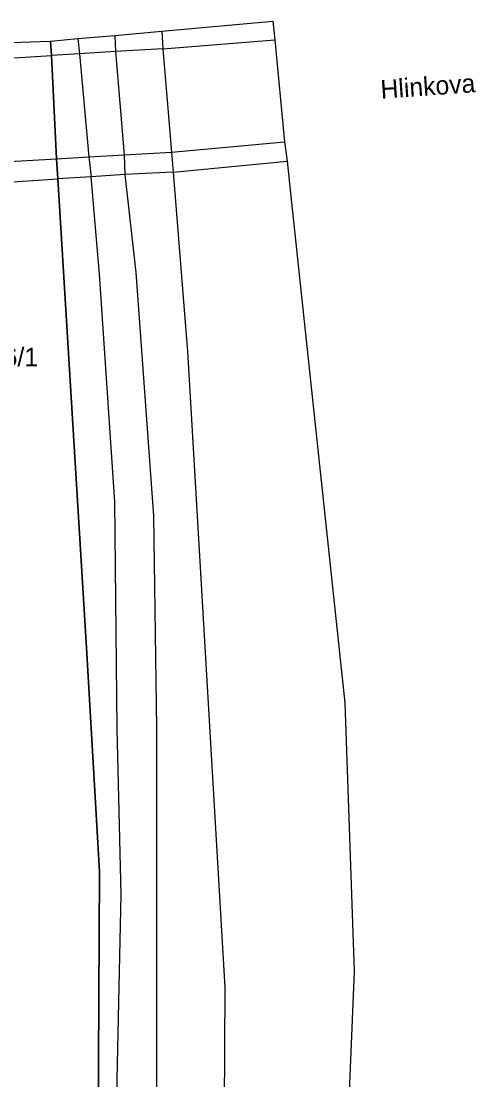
# Model space of a CAD drawing. Extents: x -262657 to -261595, y -1238015 to -1237156.
# Drawn here: x -262379.8 to -262330.6, y -1237270.1 to -1237155.7 of the extents above; entities that cross this region are included whole.
import ezdxf

# ---------------------------------------------------------------- set-up
doc = ezdxf.new("R2010")
doc.units = 0
for name, color, linetype in [('body_kn', 7, 'Continuous'), ('kladpar_hranice', 7, 'Continuous'), ('kladpar_parcelnecisla', 7, 'Continuous'), ('kladpar_plochy', 7, 'Continuous'), ('popisy', 7, 'Continuous'), ('zappar_hrandruhpozemk', 7, 'Continuous')]:
    doc.layers.add(name, color=color, linetype=linetype)

msp = doc.modelspace()

# ---------------------------------------------------------------- linework, layer by layer
at = {"layer": 'body_kn'}
for p, q in [((-262352.58, -1237155.66), (-262352.58, -1237155.66)), ((-262364.61, -1237156.73), (-262364.61, -1237156.73)), ((-262364.61, -1237156.73), (-262364.61, -1237156.73)), ((-262376.63, -1237157.82), (-262376.63, -1237157.82)), ((-262373.68, -1237157.55), (-262373.68, -1237157.55)), ((-262373.68, -1237157.55), (-262373.68, -1237157.55)), ((-262369.69, -1237157.2), (-262369.69, -1237157.2)), ((-262369.69, -1237157.2), (-262369.69, -1237157.2)), ((-262352.38, -1237157.68), (-262352.38, -1237157.68)), ((-262376.54, -1237159.38), (-262376.54, -1237159.38)), ((-262373.49, -1237159.2), (-262373.49, -1237159.2)), ((-262369.59, -1237158.94), (-262369.59, -1237158.94)), ((-262364.49, -1237158.66), (-262364.49, -1237158.66)), ((-262364.49, -1237158.66), (-262364.49, -1237158.66)), ((-262351.33, -1237168.7), (-262351.33, -1237168.7)), ((-262375.97, -1237170.53), (-262375.97, -1237170.53)), ((-262375.97, -1237170.53), (-262375.97, -1237170.53)), ((-262372.49, -1237170.32), (-262372.49, -1237170.32)), ((-262372.49, -1237170.32), (-262372.49, -1237170.32)), ((-262368.66, -1237170.11), (-262368.66, -1237170.11)), ((-262368.66, -1237170.11), (-262368.66, -1237170.11)), ((-262363.53, -1237169.82), (-262363.53, -1237169.82)), ((-262363.53, -1237169.82), (-262363.53, -1237169.82)), ((-262351.05, -1237170.78), (-262351.05, -1237170.78)), ((-262363.37, -1237171.97), (-262363.37, -1237171.97)), ((-262363.37, -1237171.97), (-262363.37, -1237171.97)), ((-262375.83, -1237172.72), (-262375.83, -1237172.72)), ((-262372.23, -1237172.48), (-262372.23, -1237172.48)), ((-262368.59, -1237172.23), (-262368.59, -1237172.23)), ((-262368.59, -1237172.23), (-262368.59, -1237172.23)), ((-262350.64, -1237174.58), (-262350.64, -1237174.58)), ((-262350.32, -1237177.64), (-262350.32, -1237177.64)), ((-262371.34, -1237183.02), (-262371.34, -1237183.02)), ((-262367.41, -1237182.84), (-262367.41, -1237182.84)), ((-262361.8, -1237191.39), (-262361.8, -1237191.39)), ((-262369.67, -1237207.63), (-262369.67, -1237207.63)), ((-262365.48, -1237209.15), (-262365.48, -1237209.15)), ((-262372.75, -1237223.4), (-262372.75, -1237223.4)), ((-262344.8, -1237229.34), (-262344.8, -1237229.34)), ((-262369.44, -1237232.16), (-262369.44, -1237232.16)), ((-262365.18, -1237232.08), (-262365.18, -1237232.08)), ((-262371.35, -1237247.59), (-262371.35, -1237247.59)), ((-262368.99, -1237250.08), (-262368.99, -1237250.08)), ((-262343.78, -1237258.35), (-262343.78, -1237258.35)), ((-262343.78, -1237258.35), (-262343.78, -1237258.35)), ((-262357.78, -1237260.12), (-262357.78, -1237260.12))]:
    msp.add_line(p, q, dxfattribs=at)
at = {"layer": 'kladpar_hranice'}
for points in [[(-262372.75, -1237403.11), (-262372.62, -1237392.55), (-262371.68, -1237316.24), (-262371.35, -1237247.59), (-262372.75, -1237223.4), (-262375.83, -1237172.72), (-262375.97, -1237170.53), (-262376.54, -1237159.38), (-262376.63, -1237157.82), (-262373.68, -1237157.55), (-262369.69, -1237157.2), (-262364.61, -1237156.73), (-262352.58, -1237155.66), (-262352.38, -1237157.68), (-262351.33, -1237168.7), (-262351.05, -1237170.78), (-262350.64, -1237174.58), (-262350.32, -1237177.64), (-262344.8, -1237229.34), (-262343.78, -1237258.35)], [(-262389.58, -1237158.25), (-262376.63, -1237157.82), (-262376.54, -1237159.38), (-262375.97, -1237170.53), (-262375.83, -1237172.72), (-262372.75, -1237223.4), (-262371.35, -1237247.59), (-262371.68, -1237316.24), (-262372.62, -1237392.55), (-262372.75, -1237403.11)], [(-262343.78, -1237258.35), (-262346.58, -1237325.38), (-262343.34, -1237325.34), (-262343.65, -1237365.15), (-262343.6, -1237424.44)]]:
    msp.add_lwpolyline(points, dxfattribs=at)
at = {"layer": 'kladpar_plochy'}
for points in [[(-262372.75, -1237403.11), (-262372.62, -1237392.55), (-262371.68, -1237316.24), (-262371.35, -1237247.59), (-262372.75, -1237223.4), (-262375.83, -1237172.72), (-262375.97, -1237170.53), (-262376.54, -1237159.38), (-262376.63, -1237157.82), (-262373.68, -1237157.55), (-262369.69, -1237157.2), (-262364.61, -1237156.73), (-262352.58, -1237155.66), (-262352.38, -1237157.68), (-262351.33, -1237168.7), (-262351.05, -1237170.78), (-262350.64, -1237174.58), (-262350.32, -1237177.64), (-262344.8, -1237229.34), (-262343.78, -1237258.35), (-262346.58, -1237325.38), (-262343.34, -1237325.34), (-262343.65, -1237365.15), (-262343.6, -1237424.44)], [(-262382.18, -1237279.11), (-262381.79, -1237257.42), (-262382.13, -1237242.28), (-262382.44, -1237239.13), (-262381.89, -1237201.8), (-262387.03, -1237202.02), (-262388.75, -1237173.56), (-262388.87, -1237171.3), (-262389.53, -1237160.15), (-262389.58, -1237158.25), (-262376.63, -1237157.82), (-262376.54, -1237159.38), (-262375.97, -1237170.53), (-262375.83, -1237172.72), (-262372.75, -1237223.4), (-262371.35, -1237247.59), (-262371.68, -1237316.24)]]:
    msp.add_lwpolyline(points, dxfattribs=at)
at = {"layer": 'zappar_hrandruhpozemk'}
for p, q in [((-262364.49, -1237158.66), (-262352.38, -1237157.68)), ((-262389.53, -1237160.15), (-262376.54, -1237159.38)), ((-262363.53, -1237169.82), (-262351.33, -1237168.7)), ((-262388.87, -1237171.3), (-262375.97, -1237170.53)), ((-262375.97, -1237170.53), (-262372.49, -1237170.32)), ((-262372.49, -1237170.32), (-262368.66, -1237170.11)), ((-262368.66, -1237170.11), (-262363.53, -1237169.82)), ((-262363.37, -1237171.97), (-262351.05, -1237170.78)), ((-262363.37, -1237171.97), (-262361.8, -1237191.39)), ((-262388.75, -1237173.56), (-262375.83, -1237172.72)), ((-262369.44, -1237232.16), (-262369.67, -1237207.63)), ((-262365.48, -1237209.15), (-262365.18, -1237232.08)), ((-262365.18, -1237232.08), (-262365.18, -1237281.88))]:
    msp.add_line(p, q, dxfattribs=at)
for points in [[(-262364.61, -1237156.73), (-262364.49, -1237158.66), (-262363.53, -1237169.82), (-262363.37, -1237171.97)], [(-262373.68, -1237157.55), (-262373.49, -1237159.2), (-262372.49, -1237170.32), (-262372.23, -1237172.48)], [(-262369.69, -1237157.2), (-262369.59, -1237158.94), (-262368.66, -1237170.11), (-262368.59, -1237172.23)], [(-262364.49, -1237158.66), (-262369.59, -1237158.94), (-262373.49, -1237159.2), (-262376.54, -1237159.38)], [(-262363.37, -1237171.97), (-262368.59, -1237172.23), (-262372.23, -1237172.48), (-262375.83, -1237172.72)], [(-262369.67, -1237207.63), (-262371.34, -1237183.02), (-262372.23, -1237172.48)], [(-262368.59, -1237172.23), (-262367.41, -1237182.84), (-262365.48, -1237209.15)], [(-262361.8, -1237191.39), (-262357.78, -1237260.12), (-262358.17, -1237331.61)], [(-262369.67, -1237281.74), (-262368.99, -1237250.08), (-262369.44, -1237232.16)]]:
    msp.add_lwpolyline(points, dxfattribs=at)

# ---------------------------------------------------------------- texts
at = {"layer": 'kladpar_parcelnecisla'}
msp.add_text('3546/1', height=2, dxfattribs=at).set_placement((-262386.16, -1237192.97))
at = {"layer": 'popisy'}
msp.add_text('Hlinkova', height=2, rotation=4, dxfattribs=at).set_placement((-262340.87, -1237164.05))

doc.saveas('drawing.dxf')
